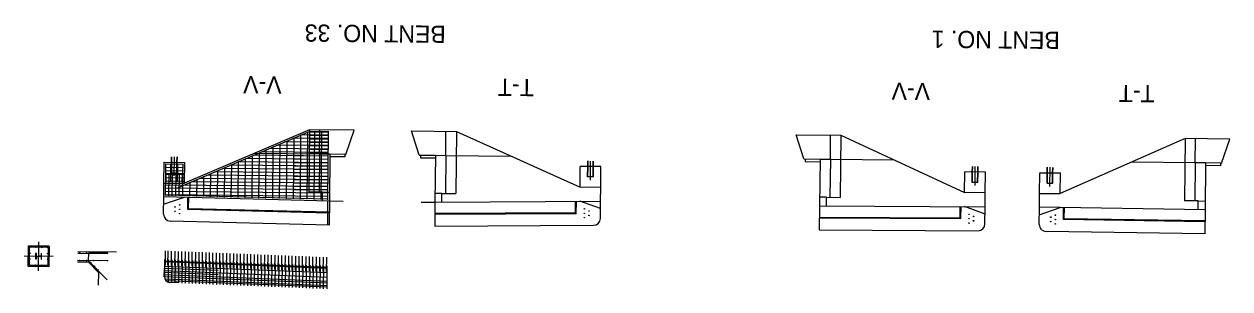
# Model space of a CAD drawing. Extents: x 632022 to 632319, y 373181 to 373252.
# Drawn here: x 632022.1 to 632196.8, y 373213.6 to 373251.9 of the extents above; entities that cross this region are included whole.
import ezdxf

# ---------------------------------------------------------------- set-up
doc = ezdxf.new("R2010")
doc.units = 0
for name, color, linetype in [('B_Boring', 7, 'Continuous'), ('BD-EXIST-OSB', 7, 'Continuous'), ('BD-LEGEND', 7, 'Continuous'), ('BD-PROP-COSS', 7, 'Continuous'), ('BD-REMOVE', 7, 'Continuous'), ('R_Border_Scale', 7, 'Continuous'), ('R_Road Edge of Travel', 7, 'Continuous'), ('R_Shade Removal', 7, 'Continuous'), ('R_Wall', 7, 'Continuous')]:
    doc.layers.add(name, color=color, linetype=linetype)

msp = doc.modelspace()

# ---------------------------------------------------------------- linework, layer by layer
at = {"layer": 'B_Boring'}
for p, q in [((632084.74, 373236.4), (632084.65, 373227.38)), ((632190.32, 373235.35), (632190.23, 373226.33)), ((632083.2, 373232.92), (632083.15, 373227.4)), ((632191.78, 373231.83), (632191.73, 373226.31)), ((632082.64, 373226.15), (632082.65, 373227.4)), ((632082.65, 373227.4), (632084.65, 373227.38)), ((632045.82, 373225.07), (632045.84, 373226.82)), ((632045.95, 373225.19), (632045.97, 373226.82)), ((632105.63, 373225.2), (632102.64, 373226.27)), ((632192.23, 373226.31), (632190.23, 373226.33)), ((632192.21, 373225.06), (632192.23, 373226.31)), ((632045.95, 373225.19), (632045.82, 373225.07)), ((632066.32, 373224.55), (632045.82, 373225.06)), ((632066.32, 373224.67), (632045.95, 373225.18)), ((632137.34, 373223.97), (632157.72, 373223.87)), ((632137.34, 373223.85), (632157.84, 373223.75)), ((632157.72, 373223.87), (632157.73, 373225.5)), ((632157.72, 373223.87), (632157.84, 373223.75)), ((632157.84, 373223.75), (632157.86, 373225.5)), ((632169.2, 373224.32), (632172.21, 373225.35))]:
    msp.add_line(p, q, dxfattribs=at)
at = {"layer": 'BD-EXIST-OSB'}
for p, q in [((632023.81, 373217.86), (632023.82, 373218.72)), ((632023.86, 373218.72), (632023.82, 373218.72)), ((632023.86, 373218.72), (632023.86, 373218.31)), ((632024.6, 373218.71), (632024.65, 373218.71)), ((632024.6, 373218.71), (632024.6, 373218.31)), ((632024.64, 373217.85), (632024.65, 373218.71)), ((632023.86, 373217.86), (632023.81, 373217.86)), ((632023.86, 373218.31), (632024.23, 373218.31)), ((632023.86, 373218.27), (632024.23, 373218.26)), ((632023.86, 373218.27), (632023.86, 373217.86)), ((632024.6, 373218.31), (632024.23, 373218.31)), ((632024.6, 373218.26), (632024.23, 373218.26)), ((632024.6, 373218.26), (632024.6, 373217.85)), ((632024.6, 373217.85), (632024.64, 373217.85))]:
    msp.add_line(p, q, dxfattribs=at)
at = {"layer": 'BD-LEGEND'}
for p, q in [((632022.71, 373216.8), (632022.74, 373219.8)), ((632025.74, 373219.77), (632022.74, 373219.8)), ((632025.74, 373219.77), (632025.71, 373216.77)), ((632029.89, 373218.98), (632035.48, 373218.92)), ((632029.87, 373217.48), (632031.38, 373217.46)), ((632032.87, 373215.95), (632031.38, 373217.46)), ((632025.71, 373216.77), (632022.71, 373216.8)), ((632032.87, 373215.95), (632032.85, 373214.12))]:
    msp.add_line(p, q, dxfattribs=at)
at = {"layer": 'BD-PROP-COSS'}
for p, q in [((632063.49, 373236.36), (632044.18, 373228.11)), ((632063.19, 373236.32), (632063.09, 373226.55)), ((632066.27, 373236.34), (632063.49, 373236.36)), ((632066.27, 373236.25), (632063.52, 373236.28)), ((632064.19, 373236.44), (632064.09, 373226.51)), ((632065.19, 373236.43), (632065.09, 373226.5)), ((632066.19, 373236.42), (632066.09, 373226.49)), ((632066.25, 373234.34), (632058.71, 373234.41)), ((632059.17, 373234.61), (632059.09, 373226.65)), ((632066.26, 373234.84), (632059.85, 373234.9)), ((632060.17, 373235.04), (632060.09, 373226.62)), ((632066.26, 373235.34), (632061, 373235.39)), ((632061.18, 373235.47), (632061.09, 373226.6)), ((632062.18, 373235.9), (632062.09, 373226.57)), ((632066.27, 373235.84), (632062.14, 373235.88)), ((632066.25, 373234.75), (632063.5, 373234.78)), ((632066.26, 373235.75), (632063.51, 373235.78)), ((632066.26, 373235.25), (632063.51, 373235.28)), ((632055.15, 373232.89), (632055.09, 373226.75)), ((632055.37, 373232.98), (632066.24, 373232.87)), ((632056.16, 373233.32), (632056.09, 373226.73)), ((632066.24, 373233.34), (632056.43, 373233.43)), ((632057.16, 373233.75), (632057.09, 373226.7)), ((632066.25, 373233.84), (632057.57, 373233.92)), ((632058.17, 373234.18), (632058.09, 373226.68)), ((632066.23, 373232.79), (632061.24, 373232.84)), ((632066.24, 373233.75), (632063.49, 373233.78)), ((632066.24, 373233.25), (632063.49, 373233.28)), ((632066.25, 373234.25), (632063.5, 373234.28)), ((632045.22, 373231.13), (632042.55, 373231.16)), ((632045.22, 373231.59), (632042.56, 373231.62)), ((632042.63, 373230.37), (632042.64, 373231.66)), ((632043.36, 373229.07), (632043.39, 373231.65)), ((632044.36, 373229.06), (632044.39, 373231.64)), ((632045.13, 373230.34), (632045.14, 373231.64)), ((632050.85, 373231.05), (632066.22, 373230.9)), ((632051.13, 373231.17), (632051.09, 373226.85)), ((632051.98, 373231.53), (632066.22, 373231.39)), ((632052.14, 373231.6), (632052.09, 373226.83)), ((632053.14, 373232.03), (632053.09, 373226.8)), ((632053.11, 373232.02), (632066.23, 373231.89)), ((632054.15, 373232.46), (632054.09, 373226.78)), ((632054.24, 373232.5), (632066.23, 373232.38)), ((632066.22, 373231.31), (632061.22, 373231.36)), ((632066.22, 373230.81), (632061.22, 373230.86)), ((632066.23, 373232.3), (632061.23, 373232.35)), ((632066.23, 373231.8), (632061.23, 373231.85)), ((632045.2, 373229.13), (632042.53, 373229.16)), ((632045.21, 373230.22), (632042.54, 373230.24)), ((632045.21, 373230.13), (632042.54, 373230.16)), ((632045.2, 373229.63), (632042.54, 373229.66)), ((632045.21, 373230.63), (632042.55, 373230.66)), ((632042.59, 373227.08), (632042.63, 373230.28)), ((632042.63, 373230.37), (632042.71, 373230.28)), ((632042.7, 373229.08), (632042.71, 373230.28)), ((632043.09, 373227.07), (632043.13, 373230.28)), ((632043.59, 373227.07), (632043.63, 373230.28)), ((632044.09, 373227.06), (632044.13, 373230.27)), ((632044.59, 373227.06), (632044.63, 373230.27)), ((632045.03, 373229.05), (632045.04, 373230.26)), ((632045.13, 373230.34), (632045.04, 373230.26)), ((632045.09, 373227.05), (632045.13, 373230.26)), ((632046.33, 373229.12), (632066.2, 373228.92)), ((632047.12, 373229.45), (632047.09, 373226.96)), ((632047.46, 373229.6), (632066.2, 373229.41)), ((632048.12, 373229.88), (632048.09, 373226.93)), ((632048.59, 373230.08), (632066.21, 373229.91)), ((632049.13, 373230.31), (632049.09, 373226.91)), ((632049.72, 373230.57), (632066.21, 373230.4)), ((632050.13, 373230.74), (632050.09, 373226.88)), ((632066.2, 373229.33), (632061.2, 373229.38)), ((632066.21, 373230.32), (632061.21, 373230.37)), ((632066.21, 373229.83), (632061.21, 373229.87)), ((632042.52, 373228.19), (632066.19, 373227.96)), ((632042.52, 373227.72), (632066.18, 373227.49)), ((632042.53, 373228.66), (632066.19, 373228.43)), ((632046.11, 373229.02), (632046.09, 373226.98)), ((632066.19, 373228.34), (632061.19, 373228.39)), ((632066.19, 373227.87), (632061.19, 373227.92)), ((632066.2, 373228.84), (632061.2, 373228.89)), ((632042.51, 373227.25), (632066.18, 373227.02)), ((632066.17, 373226.55), (632042.51, 373227.16)), ((632022.86, 373218.97), (632022.87, 373219.63)), ((632025.58, 373219.61), (632022.87, 373219.63)), ((632022.88, 373216.97), (632022.91, 373219.67)), ((632023.58, 373219.67), (632022.91, 373219.67)), ((632025.58, 373219.61), (632025.55, 373216.94)), ((632029.88, 373218.73), (632034.24, 373218.69)), ((632031.45, 373217.63), (632031.47, 373218.8)), ((632031.47, 373218.8), (632034.24, 373218.77)), ((632042.58, 373216.99), (632042.6, 373219.08)), ((632042.93, 373219.06), (632042.91, 373216.98)), ((632043.43, 373219.04), (632043.41, 373216.96)), ((632043.93, 373219.02), (632043.91, 373216.94)), ((632044.43, 373219), (632044.41, 373216.92)), ((632044.93, 373218.98), (632044.91, 373216.9)), ((632045.43, 373218.96), (632045.41, 373216.88)), ((632045.93, 373218.94), (632045.91, 373216.86)), ((632046.43, 373218.92), (632046.41, 373216.84)), ((632046.93, 373218.9), (632046.91, 373216.82)), ((632047.43, 373218.88), (632047.41, 373216.8)), ((632047.93, 373218.86), (632047.91, 373216.78)), ((632048.43, 373218.84), (632048.41, 373216.76)), ((632048.93, 373218.82), (632048.91, 373216.74)), ((632049.43, 373218.8), (632049.41, 373216.72)), ((632049.93, 373218.78), (632049.91, 373216.7)), ((632050.43, 373218.76), (632050.41, 373216.68)), ((632050.93, 373218.74), (632050.91, 373216.66)), ((632051.43, 373218.72), (632051.41, 373216.64)), ((632051.93, 373218.7), (632051.91, 373216.62)), ((632052.43, 373218.68), (632052.41, 373216.6)), ((632052.93, 373218.66), (632052.91, 373216.58)), ((632053.43, 373218.64), (632053.41, 373216.56)), ((632053.93, 373218.62), (632053.91, 373216.54)), ((632054.43, 373218.6), (632054.41, 373216.52)), ((632054.93, 373218.58), (632054.91, 373216.5)), ((632055.43, 373218.56), (632055.41, 373216.48)), ((632025.55, 373216.94), (632022.88, 373216.97)), ((632029.87, 373217.73), (632034.23, 373217.69)), ((632034.14, 373214.89), (632031.45, 373217.63)), ((632066.07, 373216.51), (632042.41, 373217.46)), ((632066.07, 373215.89), (632042.41, 373216.83)), ((632066.07, 373216.64), (632042.42, 373217.58)), ((632042.48, 373215.25), (632042.5, 373217.83)), ((632043, 373217.81), (632042.97, 373214.56)), ((632043.5, 373217.79), (632043.47, 373214.46)), ((632044, 373217.77), (632043.97, 373214.44)), ((632044.5, 373217.75), (632044.47, 373214.42)), ((632045, 373217.73), (632044.97, 373214.4)), ((632045.5, 373217.71), (632045.47, 373214.38)), ((632046, 373217.69), (632045.97, 373214.36)), ((632046.5, 373217.67), (632046.47, 373214.34)), ((632047, 373217.65), (632046.97, 373214.32)), ((632047.5, 373217.63), (632047.47, 373214.3)), ((632048, 373217.61), (632047.97, 373214.28)), ((632048.5, 373217.59), (632048.47, 373214.26)), ((632049, 373217.57), (632048.97, 373214.24)), ((632049.5, 373217.55), (632049.47, 373214.22)), ((632050, 373217.53), (632049.97, 373214.2)), ((632050.5, 373217.51), (632050.47, 373214.18)), ((632051, 373217.49), (632050.97, 373214.16)), ((632051.5, 373217.47), (632051.47, 373214.14)), ((632052, 373217.45), (632051.97, 373214.12)), ((632052.5, 373217.43), (632052.47, 373214.1)), ((632053, 373217.41), (632052.96, 373214.08)), ((632053.5, 373217.39), (632053.46, 373214.06)), ((632054, 373217.37), (632053.96, 373214.04)), ((632054.5, 373217.35), (632054.46, 373214.02)), ((632055, 373217.33), (632054.96, 373214)), ((632055.5, 373217.31), (632055.46, 373213.98)), ((632055.93, 373218.54), (632055.91, 373216.46)), ((632056, 373217.29), (632055.96, 373213.96)), ((632056.43, 373218.52), (632056.41, 373216.44)), ((632056.5, 373217.27), (632056.46, 373213.94)), ((632056.93, 373218.5), (632056.91, 373216.42)), ((632057, 373217.25), (632056.96, 373213.92)), ((632057.43, 373218.48), (632057.4, 373216.4)), ((632057.5, 373217.23), (632057.46, 373213.9)), ((632057.93, 373218.46), (632057.9, 373216.38)), ((632058, 373217.21), (632057.96, 373213.88)), ((632058.43, 373218.44), (632058.4, 373216.36)), ((632058.5, 373217.19), (632058.46, 373213.86)), ((632058.93, 373218.42), (632058.9, 373216.34)), ((632059, 373217.17), (632058.96, 373213.84)), ((632059.42, 373218.4), (632059.4, 373216.32)), ((632059.5, 373217.15), (632059.46, 373213.82)), ((632059.92, 373218.38), (632059.9, 373216.3)), ((632060, 373217.13), (632059.96, 373213.8)), ((632060.42, 373218.36), (632060.4, 373216.28)), ((632060.5, 373217.11), (632060.46, 373213.78)), ((632060.92, 373218.34), (632060.9, 373216.26)), ((632061, 373217.09), (632060.96, 373213.76)), ((632061.42, 373218.32), (632061.4, 373216.24)), ((632061.5, 373217.07), (632061.46, 373213.74)), ((632061.92, 373218.3), (632061.9, 373216.22)), ((632061.99, 373217.05), (632061.96, 373213.72)), ((632062.42, 373218.28), (632062.4, 373216.2)), ((632062.49, 373217.03), (632062.46, 373213.7)), ((632062.92, 373218.26), (632062.9, 373216.18)), ((632062.99, 373217.01), (632062.96, 373213.68)), ((632063.42, 373218.24), (632063.4, 373216.16)), ((632063.49, 373216.99), (632063.46, 373213.66)), ((632063.92, 373218.22), (632063.9, 373216.14)), ((632063.99, 373216.97), (632063.96, 373213.64)), ((632064.42, 373218.2), (632064.4, 373216.12)), ((632064.49, 373216.95), (632064.46, 373213.62)), ((632064.92, 373218.18), (632064.9, 373216.1)), ((632064.99, 373216.93), (632064.96, 373213.6)), ((632065.42, 373218.17), (632065.4, 373216.08)), ((632065.49, 373216.91), (632065.46, 373213.58)), ((632065.92, 373218.15), (632065.9, 373216.06)), ((632065.99, 373216.89), (632065.96, 373213.56)), ((632066.05, 373214.39), (632042.39, 373215.33)), ((632066.06, 373215.22), (632042.4, 373216.17)), ((632050.23, 373215.6), (632042.4, 373215.92)), ((632066.05, 373214.64), (632042.4, 373215.58)), ((632050.24, 373216.23), (632042.41, 373216.54)), ((632042.43, 373215.31), (632042.45, 373216.56)), ((632066.05, 373213.81), (632042.61, 373214.74)), ((632066.05, 373214.01), (632042.62, 373214.95)), ((632044.44, 373214.46), (632043.19, 373214.51))]:
    msp.add_line(p, q, dxfattribs=at)
for centre in [(632022.94, 373218.73), (632022.95, 373219.59), (632023.81, 373219.58), (632024.67, 373219.57), (632025.53, 373218.7), (632025.53, 373219.56), (632030.16, 373218.77), (632031.16, 373218.76), (632032.16, 373218.75), (632033.16, 373218.74), (632034.16, 373218.73), (632022.93, 373217.01), (632022.93, 373217.87), (632023.79, 373217), (632024.65, 373216.99), (632025.51, 373216.98), (632025.52, 373217.84), (632030.15, 373217.69), (632031.15, 373217.68), (632031.74, 373217.4), (632032.15, 373217.67), (632032.28, 373216.85), (632033.15, 373217.66), (632034.15, 373217.65), (632032.81, 373216.31)]:
    msp.add_circle(centre, 0.0417, dxfattribs=at)
msp.add_arc((632043.23, 373215.3), 0.792, 179.4304, 267.712, dxfattribs=at)
at = {"layer": 'R_Border_Scale'}
for p, q in [((632064.9, 373233.1), (632064.94, 373236.6)), ((632083.2, 373232.92), (632083.24, 373236.42)), ((632138.93, 373232.36), (632138.96, 373235.86)), ((632191.78, 373231.83), (632191.82, 373235.33)), ((632064.9, 373233.1), (632055.44, 373233.19)), ((632066.4, 373233.08), (632064.9, 373233.1)), ((632081.7, 373232.93), (632083.2, 373232.92)), ((632083.2, 373232.92), (632092.67, 373232.82)), ((632137.43, 373232.37), (632138.93, 373232.36)), ((632138.93, 373232.36), (632148.15, 373232.27)), ((632191.78, 373231.83), (632182.56, 373231.92)), ((632193.28, 373231.82), (632191.78, 373231.83)), ((632065.35, 373227.57), (632066.35, 373227.56)), ((632082.65, 373227.4), (632081.65, 373227.41)), ((632066.34, 373226.3), (632042.34, 373226.91)), ((632081.64, 373226.15), (632105.64, 373226.28)), ((632137.36, 373225.6), (632161.36, 373225.48)), ((632138.37, 373226.84), (632137.37, 373226.85)), ((632192.23, 373226.31), (632193.23, 373226.3)), ((632193.21, 373225.04), (632169.22, 373225.4))]:
    msp.add_line(p, q, dxfattribs=at)
at = {"layer": 'R_Road Edge of Travel'}
for p, q in [((632043.47, 373231.9), (632043.48, 373232.71)), ((632043.52, 373231.9), (632043.53, 373232.7)), ((632044.26, 373231.89), (632044.27, 373232.7)), ((632044.31, 373231.89), (632044.32, 373232.7)), ((632043.46, 373230.4), (632043.47, 373231.9)), ((632043.51, 373230.4), (632043.52, 373231.9)), ((632044.25, 373230.39), (632044.26, 373231.89)), ((632044.29, 373230.39), (632044.31, 373231.89)), ((632103.76, 373229.8), (632103.77, 373231.3)), ((632103.77, 373231.3), (632103.78, 373232.11)), ((632103.8, 373229.8), (632103.82, 373231.3)), ((632103.82, 373231.3), (632103.83, 373232.11)), ((632104.54, 373229.79), (632104.56, 373231.29)), ((632104.56, 373231.29), (632104.57, 373232.1)), ((632104.59, 373229.79), (632104.61, 373231.29)), ((632104.61, 373231.29), (632104.61, 373232.1)), ((632159.49, 373230.5), (632159.5, 373231.3)), ((632159.54, 373230.5), (632159.55, 373231.3)), ((632160.28, 373230.49), (632160.29, 373231.29)), ((632160.33, 373230.49), (632160.33, 373231.29)), ((632170.35, 373230.39), (632170.36, 373231.19)), ((632170.4, 373230.39), (632170.4, 373231.19)), ((632171.13, 373230.38), (632171.14, 373231.18)), ((632171.18, 373230.38), (632171.19, 373231.18)), ((632043.46, 373230.4), (632044.29, 373230.39)), ((632104.59, 373229.79), (632103.76, 373229.8)), ((632159.48, 373229), (632159.49, 373230.5)), ((632159.52, 373229), (632159.54, 373230.5)), ((632160.26, 373228.99), (632160.28, 373230.49)), ((632160.31, 373228.99), (632160.33, 373230.49)), ((632170.33, 373228.89), (632170.35, 373230.39)), ((632170.38, 373228.89), (632170.4, 373230.39)), ((632171.12, 373228.88), (632171.13, 373230.38)), ((632171.17, 373228.88), (632171.18, 373230.38)), ((632160.31, 373228.99), (632159.48, 373229)), ((632170.33, 373228.89), (632171.17, 373228.88))]:
    msp.add_line(p, q, dxfattribs=at)
at = {"layer": 'R_Shade Removal'}
for p, q in [((632063.44, 373236.61), (632045.36, 373228.88)), ((632063.44, 373236.61), (632063.35, 373227.59)), ((632069.94, 373236.55), (632063.44, 373236.61)), ((632068.74, 373233.06), (632069.94, 373236.55)), ((632078.24, 373236.47), (632084.74, 373236.4)), ((632079.37, 373232.96), (632078.24, 373236.47)), ((632084.74, 373236.4), (632102.66, 373228.31)), ((632133.96, 373235.91), (632140.46, 373235.84)), ((632135.09, 373232.4), (632133.96, 373235.91)), ((632140.46, 373235.84), (632140.37, 373226.82)), ((632140.46, 373235.84), (632158.38, 373227.51)), ((632190.32, 373235.35), (632172.24, 373227.37)), ((632196.81, 373235.28), (632190.32, 373235.35)), ((632195.61, 373231.79), (632196.81, 373235.28)), ((632064.9, 373233.1), (632064.85, 373227.58)), ((632066.4, 373233.08), (632066.34, 373226.3)), ((632068.74, 373233.06), (632066.4, 373233.08)), ((632068.57, 373232.69), (632066.4, 373232.71)), ((632068.57, 373233.06), (632068.57, 373232.69)), ((632079.37, 373232.96), (632081.7, 373232.93)), ((632079.54, 373232.95), (632079.53, 373232.58)), ((632079.53, 373232.58), (632081.7, 373232.56)), ((632081.7, 373232.93), (632081.64, 373226.15)), ((632042.36, 373228.91), (632042.39, 373231.91)), ((632042.39, 373231.91), (632045.39, 373231.88)), ((632045.36, 373228.88), (632045.39, 373231.88)), ((632102.66, 373228.31), (632102.69, 373231.31)), ((632105.69, 373231.28), (632102.69, 373231.31)), ((632105.66, 373228.28), (632105.69, 373231.28)), ((632135.09, 373232.4), (632137.43, 373232.37)), ((632135.26, 373232.39), (632135.26, 373232.02)), ((632135.26, 373232.02), (632137.42, 373232)), ((632137.43, 373232.37), (632137.36, 373225.6)), ((632138.93, 373232.36), (632138.87, 373226.84)), ((632193.28, 373231.82), (632193.21, 373225.04)), ((632195.61, 373231.79), (632193.28, 373231.82)), ((632195.44, 373231.42), (632193.28, 373231.44)), ((632195.45, 373231.8), (632195.44, 373231.42)), ((632158.38, 373227.51), (632158.41, 373230.51)), ((632161.41, 373230.48), (632158.41, 373230.51)), ((632161.38, 373227.48), (632161.41, 373230.48)), ((632169.24, 373227.4), (632169.26, 373230.4)), ((632169.26, 373230.4), (632172.26, 373230.37)), ((632172.24, 373227.37), (632172.26, 373230.37)), ((632042.34, 373226.91), (632042.36, 373228.91)), ((632042.36, 373228.91), (632045.36, 373228.88)), ((632065.35, 373227.57), (632063.35, 373227.59)), ((632065.34, 373226.32), (632065.35, 373227.57)), ((632105.66, 373228.28), (632102.66, 373228.31)), ((632105.64, 373226.28), (632105.66, 373228.28)), ((632161.38, 373227.48), (632158.38, 373227.51)), ((632161.36, 373225.48), (632161.38, 373227.48)), ((632169.22, 373225.4), (632169.24, 373227.4)), ((632169.24, 373227.4), (632172.24, 373227.37)), ((632042.32, 373224.4), (632042.34, 373226.91)), ((632042.33, 373225.83), (632045.34, 373226.84)), ((632066.09, 373226.3), (632066.05, 373222.8)), ((632066.34, 373226.3), (632066.3, 373222.8)), ((632068.34, 373226.25), (632066.34, 373226.3)), ((632079.64, 373226.13), (632081.64, 373226.15)), ((632081.64, 373226.15), (632081.6, 373222.65)), ((632102, 373224.64), (632102.01, 373226.26)), ((632102.12, 373224.51), (632102.14, 373226.26)), ((632105.61, 373223.77), (632105.64, 373226.28)), ((632137.36, 373225.6), (632137.32, 373222.1)), ((632138.36, 373225.59), (632138.37, 373226.84)), ((632138.37, 373226.84), (632140.37, 373226.82)), ((632081.62, 373224.52), (632102, 373224.63)), ((632081.62, 373224.4), (632102.12, 373224.5)), ((632102, 373224.64), (632102.12, 373224.51)), ((632161.35, 373224.39), (632158.36, 373225.49)), ((632161.33, 373222.97), (632161.36, 373225.48)), ((632169.19, 373222.89), (632169.22, 373225.4)), ((632172.7, 373223.6), (632172.71, 373225.35)), ((632172.82, 373223.72), (632172.84, 373225.35)), ((632193.21, 373225.04), (632193.18, 373221.54)), ((632066.3, 373222.8), (632043.29, 373223.39)), ((632081.6, 373222.65), (632104.62, 373222.78)), ((632137.32, 373222.1), (632160.33, 373221.98)), ((632172.82, 373223.72), (632172.7, 373223.6)), ((632193.2, 373223.29), (632172.7, 373223.6)), ((632193.2, 373223.41), (632172.82, 373223.72)), ((632193.18, 373221.54), (632170.18, 373221.88))]:
    msp.add_line(p, q, dxfattribs=at)
for centre in [(632044.66, 373225.74), (632043.99, 373225.44), (632043.99, 373224.81), (632044.65, 373224.47), (632044.66, 373225.1), (632103.28, 373223.88), (632103.29, 373225.16), (632103.29, 373224.52), (632103.95, 373224.21), (632103.96, 373224.85), (632159.02, 373224.37), (632159.68, 373224.07), (632170.87, 373223.96), (632171.54, 373224.25), (632159, 373223.1), (632159.01, 373223.74), (632159.67, 373223.43), (632170.86, 373223.32), (632171.52, 373222.98), (632171.53, 373223.61)]:
    msp.add_circle(centre, 0.0417, dxfattribs=at)
for centre, start, end in [((632043.32, 373224.39), 179.4304, 268.5309), ((632104.61, 373223.78), 270.3298, 359.4304), ((632160.33, 373222.98), 269.7168, 359.4304), ((632170.19, 373222.88), 179.4304, 269.1439)]:
    msp.add_arc(centre, 1, start, end, dxfattribs=at)
at = {"layer": 'R_Wall'}
for p, q in [((632043.87, 373229.94), (632043.9, 373232.7)), ((632104.17, 373229.34), (632104.2, 373232.1)), ((632159.89, 373228.53), (632159.92, 373231.3)), ((632170.75, 373228.42), (632170.77, 373231.19)), ((632024.21, 373216.2), (632024.25, 373220.4)), ((632026.32, 373218.26), (632022.12, 373218.31))]:
    msp.add_line(p, q, dxfattribs=at)

# ---------------------------------------------------------------- texts
at = {"layer": 'BD-REMOVE'}
for s, p in [('BENT NO. 33', (632083.22, 373251.71)), ('BENT NO. 1', (632172.19, 373250.83)), ('V-V', (632059.44, 373244.36)), ('T-T', (632095.98, 373243.99)), ('V-V', (632153.39, 373243.42)), ('T-T', (632185.93, 373243.1))]:
    msp.add_text(s, height=2.5, rotation=179.4304, dxfattribs=at).set_placement(p)

doc.saveas('drawing.dxf')
